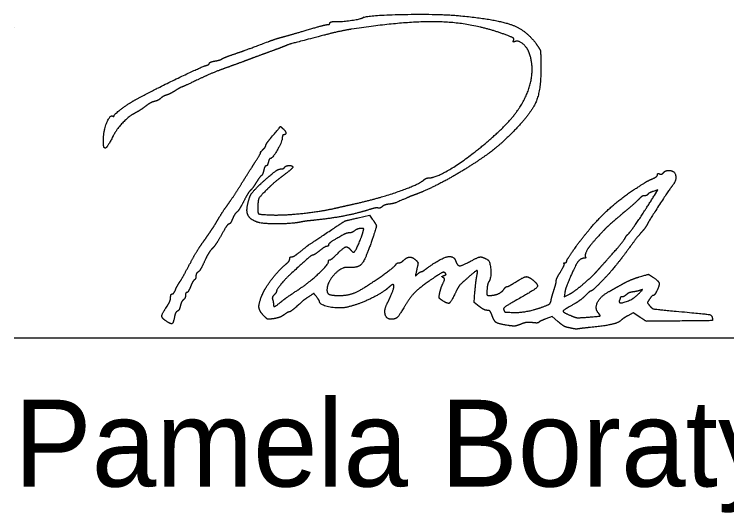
# Model space of a CAD drawing. Extents: x -8.3 to 34, y 0 to 22.
# Drawn here: x 24.426 to 25.575, y 2.669 to 3.473 of the extents above; entities that cross this region are included whole.
import ezdxf

# ---------------------------------------------------------------- set-up
doc = ezdxf.new("R2010")
doc.units = 0
doc.layers.add('SH_Data', color=7, linetype='Continuous')
doc.layers.add('SH_Text', color=7, linetype='Continuous')

msp = doc.modelspace()

# ---------------------------------------------------------------- linework, layer by layer
at = {"layer": 'SH_Data'}
for p, q in [((24.4262, 3.4514), (24.4262, 3.4514)), ((24.4262, 2.9514), (27.9262, 2.9514))]:
    msp.add_line(p, q, dxfattribs=at)
at = {"layer": 'SH_Text'}
for points in [[(25.458, 3.1809), (25.4634, 3.1898), (25.4561, 3.1872)], [(24.9807, 3.1447), (24.9987, 3.1488), (25.0034, 3.1426)], [(25.1757, 3.0019), (25.1673, 3.0082), (25.1688, 3.0253)], [(25.3137, 3.0239), (25.3126, 3.0174), (25.3213, 3.0218)], [(25.4345, 2.9846), (25.4238, 2.9914), (25.4155, 2.9869)], [(25.3026, 2.9776), (25.2935, 2.9858), (25.2829, 2.9818)]]:
    msp.add_lwpolyline(points, dxfattribs=at)
for points in [[(24.9881, 3.4673), (24.9949, 3.4715), (25.1119, 3.4738), (25.1463, 3.4704)], [(25.1463, 3.4704), (25.2056, 3.4645), (25.2531, 3.4463), (25.2689, 3.4232)], [(24.9314, 3.4563), (24.9334, 3.4563), (24.9351, 3.4575), (24.9351, 3.4588)], [(24.9351, 3.4588), (24.9351, 3.4602), (24.9392, 3.4612), (24.9441, 3.4611)], [(24.9441, 3.4611), (24.9537, 3.4608), (24.9847, 3.4652), (24.9881, 3.4673)], [(25.2188, 3.4396), (25.1683, 3.4586), (25.0603, 3.4626), (24.9699, 3.4488)], [(24.8595, 3.4365), (24.8648, 3.4379), (24.8823, 3.4429), (24.8984, 3.4477)], [(24.8984, 3.4477), (24.9145, 3.4524), (24.9293, 3.4563), (24.9314, 3.4563)], [(24.9699, 3.4488), (24.9607, 3.4474), (24.9407, 3.4431), (24.9255, 3.4391)], [(24.8355, 3.4287), (24.8434, 3.4317), (24.8542, 3.4352), (24.8595, 3.4365)], [(24.9255, 3.4391), (24.8745, 3.4259), (24.8702, 3.4247), (24.8595, 3.4204)], [(25.2311, 3.431), (25.2321, 3.4335), (25.2287, 3.4359), (25.2188, 3.4396)], [(24.7791, 3.4081), (24.7938, 3.4132), (24.8003, 3.4156), (24.8355, 3.4287)], [(25.2335, 3.4289), (25.2309, 3.4279), (25.2302, 3.4286), (25.2311, 3.431)], [(25.2569, 3.409), (25.2537, 3.4188), (25.2392, 3.4311), (25.2335, 3.4289)], [(25.2689, 3.4232), (25.2739, 3.416), (25.2748, 3.4116), (25.2751, 3.3938)], [(24.8367, 3.4119), (24.8268, 3.4083), (24.8117, 3.4027), (24.8031, 3.3995)], [(24.8595, 3.4204), (24.8569, 3.4193), (24.8466, 3.4155), (24.8367, 3.4119)], [(24.7497, 3.3975), (24.7547, 3.3984), (24.7598, 3.4), (24.7611, 3.401)], [(24.7611, 3.401), (24.7624, 3.4019), (24.7705, 3.4052), (24.7791, 3.4081)], [(24.8031, 3.3995), (24.7945, 3.3962), (24.7783, 3.3903), (24.7671, 3.3863)], [(25.2114, 3.2878), (25.2424, 3.3172), (25.2662, 3.3808), (25.2569, 3.409)], [(24.6231, 3.3359), (24.6534, 3.3522), (24.727, 3.3878), (24.7353, 3.3903)], [(24.7353, 3.3903), (24.7383, 3.3912), (24.7407, 3.3928), (24.7407, 3.3938)], [(24.7407, 3.3938), (24.7407, 3.3949), (24.7448, 3.3966), (24.7497, 3.3975)], [(25.2751, 3.3938), (25.2759, 3.353), (25.2598, 3.3133), (25.2304, 3.2834)], [(24.7671, 3.3863), (24.7559, 3.3823), (24.7356, 3.3738), (24.7219, 3.3673)], [(24.7219, 3.3673), (24.7082, 3.3608), (24.6966, 3.3555), (24.6961, 3.3555)], [(24.6961, 3.3555), (24.6955, 3.3555), (24.691, 3.353), (24.6861, 3.3499)], [(24.6712, 3.3424), (24.668, 3.3414), (24.6639, 3.339), (24.6621, 3.3372)], [(24.6861, 3.3499), (24.6812, 3.3468), (24.6745, 3.3434), (24.6712, 3.3424)], [(24.5871, 3.3093), (24.5871, 3.3115), (24.6125, 3.3302), (24.6231, 3.3359)], [(24.6524, 3.3324), (24.6488, 3.3315), (24.6421, 3.3279), (24.6375, 3.3243)], [(24.6621, 3.3372), (24.6603, 3.3354), (24.6559, 3.3332), (24.6524, 3.3324)], [(24.6375, 3.3243), (24.6329, 3.3207), (24.6258, 3.3161), (24.6216, 3.314)], [(24.57, 3.2715), (24.5701, 3.2846), (24.5807, 3.3112), (24.5848, 3.3087)], [(24.5848, 3.3087), (24.5861, 3.3079), (24.5871, 3.3082), (24.5871, 3.3093)], [(24.6216, 3.314), (24.6112, 3.3086), (24.5913, 3.2878), (24.5851, 3.2757)], [(24.8373, 3.2704), (24.8559, 3.2925), (24.8552, 3.292), (24.8593, 3.2886)], [(24.8593, 3.2886), (24.8635, 3.285), (24.8645, 3.2787), (24.8607, 3.2787)], [(25.0947, 3.2091), (25.1088, 3.2091), (25.1769, 3.255), (25.2114, 3.2878)], [(24.5851, 3.2757), (24.5785, 3.2628), (24.5732, 3.2559), (24.5713, 3.2578)], [(24.8583, 3.2737), (24.8583, 3.2681), (24.8424, 3.2403), (24.8392, 3.2403)], [(24.8607, 3.2787), (24.8594, 3.2787), (24.8583, 3.2765), (24.8583, 3.2737)], [(25.2304, 3.2834), (25.2118, 3.2645), (25.1794, 3.2396), (25.1489, 3.2207)], [(24.5713, 3.2578), (24.5705, 3.2586), (24.5699, 3.2647), (24.57, 3.2715)], [(24.8271, 3.2547), (24.8298, 3.2574), (24.8319, 3.2605), (24.8319, 3.2617)], [(24.8319, 3.2617), (24.8319, 3.2629), (24.8344, 3.2668), (24.8373, 3.2704)], [(24.8234, 3.2499), (24.8228, 3.2499), (24.8245, 3.2521), (24.8271, 3.2547)], [(24.8144, 3.2343), (24.8199, 3.2429), (24.824, 3.2499), (24.8234, 3.2499)], [(24.8392, 3.2403), (24.8381, 3.2403), (24.8366, 3.2376), (24.8357, 3.2343)], [(24.7923, 3.1993), (24.7989, 3.2099), (24.8089, 3.2257), (24.8144, 3.2343)], [(24.8321, 3.2283), (24.8309, 3.2283), (24.8292, 3.2251), (24.8283, 3.2212)], [(24.8357, 3.2343), (24.8349, 3.231), (24.8333, 3.2283), (24.8321, 3.2283)], [(24.8619, 3.2259), (24.8637, 3.2289), (24.8751, 3.2292), (24.8751, 3.2263)], [(24.8235, 3.1994), (24.8392, 3.214), (24.852, 3.2235), (24.8559, 3.2235)], [(24.8283, 3.2212), (24.8275, 3.2172), (24.8257, 3.2134), (24.8244, 3.2126)], [(24.8559, 3.2235), (24.8584, 3.2235), (24.8611, 3.2246), (24.8619, 3.2259)], [(24.8751, 3.2263), (24.8751, 3.2252), (24.8684, 3.2193), (24.8601, 3.2132)], [(25.1489, 3.2207), (25.1297, 3.2089), (25.0884, 3.1879), (25.0743, 3.1828)], [(25.4631, 3.2141), (25.4631, 3.2156), (25.4647, 3.2163), (25.4666, 3.2155)], [(25.4666, 3.2155), (25.4684, 3.2148), (25.4713, 3.2158), (25.4728, 3.2177)], [(25.4728, 3.2177), (25.4744, 3.2196), (25.4781, 3.2211), (25.481, 3.2211)], [(25.481, 3.2211), (25.4905, 3.2211), (25.4942, 3.2051), (25.4868, 3.1961)], [(24.8244, 3.2126), (24.8232, 3.2118), (24.8194, 3.2066), (24.816, 3.2011)], [(24.8601, 3.2132), (24.8519, 3.2071), (24.8394, 3.1962), (24.8323, 3.1891)], [(24.9747, 3.1672), (25.0117, 3.1754), (25.0779, 3.1983), (25.0865, 3.2058)], [(25.0865, 3.2058), (25.0886, 3.2076), (25.0923, 3.2091), (25.0947, 3.2091)], [(25.4263, 3.1908), (25.4453, 3.203), (25.4471, 3.2041), (25.4553, 3.2078)], [(25.4553, 3.2078), (25.4596, 3.2097), (25.4631, 3.2126), (25.4631, 3.2141)], [(24.7706, 3.1663), (24.7759, 3.1738), (24.7857, 3.1886), (24.7923, 3.1993)], [(24.8022, 3.1647), (24.8049, 3.1778), (24.8111, 3.1878), (24.8235, 3.1994)], [(24.816, 3.2011), (24.8126, 3.1956), (24.8085, 3.1901), (24.8068, 3.1887)], [(25.4868, 3.1961), (25.4827, 3.1911), (25.4498, 3.1407), (25.4467, 3.1345)], [(24.8068, 3.1887), (24.8051, 3.1874), (24.8005, 3.1798), (24.7964, 3.1718)], [(24.8323, 3.1891), (24.8216, 3.1781), (24.8195, 3.1744), (24.8189, 3.1662)], [(25.0743, 3.1828), (25.0697, 3.1811), (25.0627, 3.1784), (25.0587, 3.1766)], [(25.3317, 3.0982), (25.354, 3.129), (25.399, 3.1731), (25.4263, 3.1908)], [(25.4474, 3.1825), (25.4466, 3.1813), (25.4443, 3.1803), (25.4421, 3.1803)], [(25.4561, 3.1872), (25.452, 3.1858), (25.4481, 3.1837), (25.4474, 3.1825)], [(24.7964, 3.1718), (24.7924, 3.1638), (24.7873, 3.1558), (24.7852, 3.154)], [(25.0587, 3.1766), (25.0416, 3.1692), (25.0367, 3.1675), (25.0301, 3.1667)], [(25.4332, 3.1749), (25.4305, 3.172), (25.4181, 3.1609), (25.4055, 3.1504)], [(25.4152, 3.1179), (25.4181, 3.1199), (25.4463, 3.1614), (25.458, 3.1809)], [(25.4421, 3.1803), (25.4399, 3.1803), (25.4359, 3.1779), (25.4332, 3.1749)], [(24.7539, 3.1407), (24.7577, 3.1473), (24.7652, 3.1589), (24.7706, 3.1663)], [(24.8175, 3.1379), (24.8071, 3.1418), (24.8, 3.1542), (24.8022, 3.1647)], [(24.8189, 3.1662), (24.8181, 3.1528), (24.8221, 3.1499), (24.8427, 3.1493)], [(24.8427, 3.1493), (24.862, 3.1488), (24.9198, 3.1549), (24.9411, 3.1597)], [(24.9411, 3.1597), (24.949, 3.1615), (24.9642, 3.1649), (24.9747, 3.1672)], [(25.0125, 3.1605), (25.0109, 3.1611), (25.0028, 3.1594), (24.9945, 3.1567)], [(25.0193, 3.1627), (25.0172, 3.1608), (25.0142, 3.1599), (25.0125, 3.1605)], [(25.0301, 3.1667), (25.0263, 3.1663), (25.0214, 3.1645), (25.0193, 3.1627)], [(24.7852, 3.154), (24.783, 3.1522), (24.7797, 3.1471), (24.7779, 3.1427)], [(24.9945, 3.1567), (24.9781, 3.1515), (24.933, 3.143), (24.9092, 3.1407)], [(25.4055, 3.1504), (25.3859, 3.1338), (25.3742, 3.1225), (25.3575, 3.1036)], [(24.7408, 3.1201), (24.7441, 3.1249), (24.75, 3.1341), (24.7539, 3.1407)], [(24.7779, 3.1427), (24.7761, 3.1383), (24.7735, 3.1347), (24.7722, 3.1347)], [(24.8888, 3.138), (24.875, 3.135), (24.8256, 3.1349), (24.8175, 3.1379)], [(24.9092, 3.1407), (24.9008, 3.1399), (24.8917, 3.1387), (24.8888, 3.138)], [(24.9267, 3.1183), (24.9584, 3.1393), (24.9598, 3.14), (24.9807, 3.1447)], [(25.0034, 3.1426), (25.01, 3.1338), (25.0098, 3.1289), (25.0021, 3.1064)], [(24.7722, 3.1347), (24.7709, 3.1347), (24.7655, 3.1268), (24.7602, 3.1172)], [(24.9749, 3.1239), (24.9723, 3.1219), (24.9684, 3.1203), (24.9661, 3.1203)], [(24.9848, 3.1275), (24.9819, 3.1274), (24.9774, 3.1258), (24.9749, 3.1239)], [(24.9881, 3.1209), (24.9898, 3.1267), (24.9893, 3.1275), (24.9848, 3.1275)], [(25.4467, 3.1345), (25.4449, 3.131), (25.441, 3.1256), (25.438, 3.1223)], [(24.7273, 3.1009), (24.7314, 3.1067), (24.7375, 3.1153), (24.7408, 3.1201)], [(24.7602, 3.1172), (24.7548, 3.1075), (24.7482, 3.0975), (24.7453, 3.095)], [(24.8875, 3.0904), (24.9012, 3.1014), (24.8993, 3.1), (24.9267, 3.1183)], [(24.9564, 3.1172), (24.942, 3.1093), (24.9327, 3.1029), (24.9327, 3.1009)], [(24.9661, 3.1203), (24.9639, 3.1203), (24.9595, 3.1189), (24.9564, 3.1172)], [(24.9734, 3.0891), (24.9752, 3.0891), (24.9849, 3.1103), (24.9881, 3.1209)], [(25.38, 3.075), (25.3954, 3.0921), (25.4089, 3.1085), (25.4113, 3.1128)], [(25.4113, 3.1128), (25.4125, 3.115), (25.4143, 3.1173), (25.4152, 3.1179)], [(25.438, 3.1223), (25.435, 3.1191), (25.4261, 3.1078), (25.4182, 3.0971)], [(24.7084, 3.0687), (24.7147, 3.0806), (24.7232, 3.0951), (24.7273, 3.1009)], [(24.9327, 3.1009), (24.9327, 3.0997), (24.9315, 3.0987), (24.9301, 3.0987)], [(25.0021, 3.1064), (24.9919, 3.0765), (24.9799, 3.0634), (24.9639, 3.0648)], [(25.3575, 3.1036), (25.3517, 3.097), (25.3454, 3.0841), (25.3469, 3.0817)], [(24.7453, 3.095), (24.7425, 3.0924), (24.7369, 3.0833), (24.733, 3.0747)], [(24.8737, 3.0819), (24.8756, 3.0819), (24.8818, 3.0857), (24.8875, 3.0904)], [(24.9183, 3.0915), (24.9133, 3.0876), (24.9083, 3.0843), (24.9072, 3.0843)], [(24.9301, 3.0987), (24.9286, 3.0987), (24.9233, 3.0955), (24.9183, 3.0915)], [(24.9471, 3.0867), (24.9573, 3.0969), (24.9638, 3.0987), (24.9687, 3.0927)], [(24.9687, 3.0927), (24.9704, 3.0908), (24.9725, 3.0891), (24.9734, 3.0891)], [(25.3167, 3.0749), (25.3167, 3.0763), (25.3235, 3.0868), (25.3317, 3.0982)], [(25.4182, 3.0971), (25.4104, 3.0865), (25.4027, 3.0763), (25.4012, 3.0745)], [(24.8649, 3.0707), (24.8679, 3.0731), (24.8703, 3.0766), (24.8703, 3.0785)], [(24.8703, 3.0785), (24.8703, 3.0804), (24.8718, 3.0819), (24.8737, 3.0819)], [(24.9072, 3.0843), (24.9053, 3.0843), (24.8968, 3.0771), (24.8715, 3.0538)], [(24.9351, 3.0771), (24.9364, 3.0771), (24.9418, 3.0815), (24.9471, 3.0867)], [(25.0539, 3.0762), (25.0589, 3.0812), (25.0688, 3.0813), (25.0738, 3.0763)], [(25.0919, 3.0637), (25.1121, 3.0788), (25.1348, 3.0844), (25.1378, 3.075)], [(25.1616, 3.0746), (25.1736, 3.0813), (25.1808, 3.082), (25.189, 3.0774)], [(25.3446, 3.0795), (25.3383, 3.0795), (25.3287, 3.0644), (25.3167, 3.0351)], [(25.3469, 3.0817), (25.3476, 3.0805), (25.3466, 3.0795), (25.3446, 3.0795)], [(24.6929, 3.0411), (24.6951, 3.0444), (24.7021, 3.0569), (24.7084, 3.0687)], [(24.733, 3.0747), (24.7291, 3.0662), (24.7244, 3.0583), (24.7225, 3.0572)], [(24.8268, 3.0225), (24.8313, 3.0329), (24.8546, 3.0624), (24.8649, 3.0707)], [(24.8867, 3.0306), (24.9022, 3.041), (24.9327, 3.0697), (24.9327, 3.074)], [(24.9327, 3.074), (24.9327, 3.0757), (24.9338, 3.0771), (24.9351, 3.0771)], [(24.9987, 3.0375), (25.0173, 3.0498), (25.0397, 3.0665), (25.0414, 3.0693)], [(25.0414, 3.0693), (25.0425, 3.071), (25.0449, 3.0723), (25.0467, 3.0723)], [(25.0467, 3.0723), (25.0485, 3.0723), (25.0517, 3.0741), (25.0539, 3.0762)], [(25.0738, 3.0763), (25.0769, 3.0732), (25.0772, 3.0707), (25.0751, 3.0615)], [(25.1378, 3.075), (25.1403, 3.0674), (25.1483, 3.0673), (25.1616, 3.0746)], [(25.189, 3.0774), (25.1934, 3.0749), (25.1951, 3.0469), (25.1912, 3.0417)], [(25.307, 3.058), (25.3108, 3.0643), (25.3134, 3.0701), (25.3126, 3.0709)], [(25.3126, 3.0709), (25.3118, 3.0717), (25.3124, 3.0723), (25.3139, 3.0723)], [(25.3139, 3.0723), (25.3155, 3.0723), (25.3167, 3.0735), (25.3167, 3.0749)], [(25.3644, 3.0575), (25.3676, 3.0611), (25.3746, 3.0689), (25.38, 3.075)], [(25.4012, 3.0745), (25.3879, 3.058), (25.3834, 3.0529), (25.3715, 3.0407)], [(24.7225, 3.0572), (24.7206, 3.0562), (24.7191, 3.0533), (24.7191, 3.0508)], [(24.9639, 3.0648), (24.9535, 3.0657), (24.9303, 3.0403), (24.9303, 3.028)], [(25.0751, 3.0615), (25.0727, 3.0513), (25.0728, 3.0508), (25.0766, 3.0543)], [(25.0766, 3.0543), (25.0789, 3.0563), (25.0815, 3.0579), (25.0825, 3.0579)], [(25.0825, 3.0579), (25.0835, 3.0579), (25.0877, 3.0605), (25.0919, 3.0637)], [(25.1206, 3.0559), (25.1188, 3.0577), (25.1129, 3.0549), (25.1004, 3.0464)], [(25.1189, 3.0517), (25.1219, 3.0528), (25.1224, 3.054), (25.1206, 3.0559)], [(25.1718, 3.0501), (25.1736, 3.0596), (25.171, 3.06), (25.1617, 3.0518)], [(25.2999, 3.0433), (25.2999, 3.0451), (25.3031, 3.0518), (25.307, 3.058)], [(25.3443, 3.0387), (25.3522, 3.0455), (25.3613, 3.054), (25.3644, 3.0575)], [(24.7166, 3.0447), (24.7153, 3.0438), (24.7124, 3.0389), (24.7104, 3.0337)], [(24.7191, 3.0508), (24.7191, 3.0483), (24.718, 3.0455), (24.7166, 3.0447)], [(24.8715, 3.0538), (24.8624, 3.0454), (24.8487, 3.0284), (24.8487, 3.0254)], [(25.1004, 3.0464), (25.0806, 3.033), (25.0634, 3.0159), (25.0551, 3.0015)], [(25.1177, 3.0482), (25.1155, 3.0496), (25.1158, 3.0505), (25.1189, 3.0517)], [(25.117, 3.0384), (25.1199, 3.0446), (25.12, 3.0468), (25.1177, 3.0482)], [(25.1617, 3.0518), (25.1458, 3.0378), (25.142, 3.0334), (25.1365, 3.022)], [(25.1688, 3.0253), (25.1696, 3.0347), (25.1709, 3.0459), (25.1718, 3.0501)], [(25.2625, 3.0441), (25.2722, 3.0365), (25.2654, 3.0286), (25.2338, 3.0109)], [(25.2343, 3.0411), (25.2473, 3.0494), (25.2549, 3.0502), (25.2625, 3.0441)], [(25.4043, 3.0367), (25.4122, 3.0412), (25.4254, 3.0469), (25.4336, 3.0494)], [(25.4336, 3.0494), (25.4477, 3.0536), (25.4489, 3.0536), (25.4547, 3.0498)], [(25.4547, 3.0498), (25.4643, 3.0435), (25.4667, 3.0361), (25.4621, 3.0271)], [(24.6861, 3.0285), (24.6876, 3.0322), (24.6907, 3.0378), (24.6929, 3.0411)], [(24.7104, 3.0337), (24.7083, 3.0286), (24.7056, 3.0243), (24.7045, 3.0243)], [(24.9503, 3.0195), (24.9633, 3.0195), (24.9824, 3.0266), (24.9987, 3.0375)], [(25.0307, 3.0333), (25.0211, 3.0242), (24.9824, 3.0054), (24.9639, 3.0009)], [(25.0278, 3.0075), (25.0319, 3.0152), (25.0383, 3.0315), (25.0383, 3.0342)], [(25.0383, 3.0342), (25.0383, 3.0373), (25.0344, 3.0368), (25.0307, 3.0333)], [(25.1119, 3.0228), (25.1127, 3.0269), (25.115, 3.034), (25.117, 3.0384)], [(25.1912, 3.0417), (25.19, 3.0401), (25.1886, 3.0344), (25.1883, 3.0291)], [(25.2152, 3.0291), (25.2171, 3.0318), (25.2196, 3.0339), (25.2208, 3.0339)], [(25.2208, 3.0339), (25.222, 3.0339), (25.2281, 3.0372), (25.2343, 3.0411)], [(25.2964, 3.0291), (25.2984, 3.0351), (25.2999, 3.0414), (25.2999, 3.0433)], [(25.3167, 3.0351), (25.3156, 3.0325), (25.3142, 3.0274), (25.3137, 3.0239)], [(25.3213, 3.0218), (25.326, 3.0243), (25.3364, 3.0319), (25.3443, 3.0387)], [(25.3715, 3.0407), (25.364, 3.033), (25.357, 3.0267), (25.3559, 3.0267)], [(25.3848, 3.0257), (25.3876, 3.0272), (25.3964, 3.0322), (25.4043, 3.0367)], [(24.6783, 3.0163), (24.6783, 3.0194), (24.6794, 3.0219), (24.6808, 3.0219)], [(24.6808, 3.0219), (24.6821, 3.0219), (24.6845, 3.0249), (24.6861, 3.0285)], [(24.7045, 3.0243), (24.7033, 3.0243), (24.7023, 3.0223), (24.7023, 3.0198)], [(24.8285, 2.9868), (24.8209, 2.9944), (24.8203, 3.0072), (24.8268, 3.0225)], [(24.8487, 3.0254), (24.8487, 3.0246), (24.847, 3.0223), (24.845, 3.0203)], [(24.8551, 3.0082), (24.8627, 3.0143), (24.8679, 3.0181), (24.8867, 3.0306)], [(24.9137, 3.017), (24.9093, 3.0228), (24.9092, 3.0228), (24.9024, 3.0184)], [(24.9303, 3.028), (24.9303, 3.0229), (24.9381, 3.0195), (24.9503, 3.0195)], [(25.1165, 3.0112), (25.1116, 3.0145), (25.1108, 3.0165), (25.1119, 3.0228)], [(25.1365, 3.022), (25.1299, 3.0083), (25.125, 3.0057), (25.1165, 3.0112)], [(25.1883, 3.0291), (25.1878, 3.0216), (25.1885, 3.0195), (25.1916, 3.0195)], [(25.1916, 3.0195), (25.1999, 3.0195), (25.2119, 3.0244), (25.2152, 3.0291)], [(25.2917, 3.0121), (25.2923, 3.0155), (25.2945, 3.0232), (25.2964, 3.0291)], [(25.3559, 3.0267), (25.3548, 3.0267), (25.351, 3.0236), (25.3473, 3.0198)], [(25.3677, 2.9913), (25.3616, 2.9987), (25.3714, 3.0185), (25.3848, 3.0257)], [(25.4017, 3.0114), (25.3992, 3.0049), (25.4247, 3.0138), (25.4331, 3.0225)], [(25.4127, 3.0207), (25.4105, 3.0188), (25.4075, 3.0171), (25.4059, 3.0171)], [(25.4237, 3.0253), (25.4199, 3.0248), (25.4149, 3.0227), (25.4127, 3.0207)], [(25.4355, 3.028), (25.4329, 3.027), (25.4276, 3.0258), (25.4237, 3.0253)], [(25.4331, 3.0225), (25.4386, 3.0281), (25.4392, 3.0294), (25.4355, 3.028)], [(25.4621, 3.0271), (25.46, 3.0229), (25.4573, 3.0195), (25.4561, 3.0195)], [(24.6725, 3.0021), (24.6757, 3.0068), (24.6783, 3.0132), (24.6783, 3.0163)], [(24.6989, 3.0125), (24.697, 3.0109), (24.6947, 3.0064), (24.6939, 3.0024)], [(24.7023, 3.0198), (24.7023, 3.0174), (24.7008, 3.014), (24.6989, 3.0125)], [(24.845, 3.0203), (24.8429, 3.0182), (24.8419, 3.015), (24.8426, 3.013)], [(24.8426, 3.013), (24.8433, 3.0111), (24.8439, 3.008), (24.8439, 3.0061)], [(24.9024, 3.0184), (24.8942, 3.013), (24.8917, 3.011), (24.8805, 3.0009)], [(24.9183, 3.0096), (24.9182, 3.0105), (24.9162, 3.0138), (24.9137, 3.017)], [(24.9639, 3.0009), (24.9511, 2.9978), (24.9185, 3.004), (24.9183, 3.0096)], [(25.2338, 3.0109), (25.2206, 3.0034), (25.2143, 2.9986), (25.2152, 2.9964)], [(25.279, 3.0014), (25.2878, 3.0048), (25.2907, 3.0073), (25.2917, 3.0121)], [(25.3473, 3.0198), (25.3437, 3.016), (25.3356, 3.0098), (25.3294, 3.0062)], [(25.4031, 3.0161), (25.4031, 3.0156), (25.4025, 3.0135), (25.4017, 3.0114)], [(25.4059, 3.0171), (25.4044, 3.0171), (25.4031, 3.0167), (25.4031, 3.0161)], [(25.4503, 3.0137), (25.4468, 3.0084), (25.4468, 3.0075), (25.4506, 3.0028)], [(25.4561, 3.0195), (25.455, 3.0195), (25.4524, 3.0169), (25.4503, 3.0137)], [(24.6708, 2.9784), (24.6638, 2.9832), (24.6643, 2.9899), (24.6725, 3.0021)], [(24.6939, 3.0024), (24.693, 2.9985), (24.6909, 2.9947), (24.6891, 2.994)], [(24.8439, 3.0061), (24.8439, 3.0013), (24.8474, 3.0019), (24.8551, 3.0082)], [(24.8805, 3.0009), (24.8757, 2.9967), (24.8708, 2.9931), (24.8697, 2.9931)], [(25.0345, 2.9811), (25.0261, 2.9811), (25.0221, 2.997), (25.0278, 3.0075)], [(25.0551, 3.0015), (25.0469, 2.9874), (25.0406, 2.9811), (25.0345, 2.9811)], [(25.1887, 2.9955), (25.1861, 2.9955), (25.1802, 2.9984), (25.1757, 3.0019)], [(25.2291, 2.9921), (25.2397, 2.9915), (25.2658, 2.9964), (25.279, 3.0014)], [(25.3294, 3.0062), (25.3114, 2.9958), (25.3104, 2.9925), (25.3233, 2.987)], [(25.4506, 3.0028), (25.4543, 2.9983), (25.4592, 2.9973), (25.4931, 2.9941)], [(24.6891, 2.994), (24.6874, 2.9934), (24.6853, 2.9892), (24.6845, 2.9848)], [(24.8447, 2.9821), (24.836, 2.9808), (24.8338, 2.9814), (24.8285, 2.9868)], [(24.8612, 2.9884), (24.8577, 2.9858), (24.8502, 2.983), (24.8447, 2.9821)], [(24.8697, 2.9931), (24.8686, 2.9931), (24.8648, 2.991), (24.8612, 2.9884)], [(25.1962, 2.9877), (25.1943, 2.9929), (25.1918, 2.9955), (25.1887, 2.9955)], [(25.2216, 2.9712), (25.2065, 2.9736), (25.1997, 2.9781), (25.1962, 2.9877)], [(25.2152, 2.9964), (25.2165, 2.993), (25.2172, 2.9928), (25.2291, 2.9921)], [(25.3233, 2.987), (25.3302, 2.984), (25.3366, 2.9834), (25.3501, 2.9845)], [(25.3501, 2.9845), (25.3697, 2.9861), (25.3714, 2.9868), (25.3677, 2.9913)], [(25.4155, 2.9869), (25.4109, 2.9844), (25.4056, 2.9808), (25.4038, 2.979)], [(25.4931, 2.9941), (25.5422, 2.9896), (25.5505, 2.988), (25.5514, 2.9832)], [(24.6845, 2.9848), (24.6827, 2.9751), (24.6785, 2.9731), (24.6708, 2.9784)], [(25.2615, 2.9757), (25.2558, 2.9765), (25.2485, 2.9755), (25.2427, 2.9732)], [(25.2716, 2.9761), (25.2712, 2.9752), (25.2667, 2.975), (25.2615, 2.9757)], [(25.2829, 2.9818), (25.2771, 2.9795), (25.272, 2.9769), (25.2716, 2.9761)], [(25.3173, 2.9681), (25.3143, 2.9687), (25.3077, 2.973), (25.3026, 2.9776)], [(25.4038, 2.979), (25.4, 2.9753), (25.3785, 2.9704), (25.3551, 2.968)], [(25.4811, 2.9781), (25.4454, 2.9778), (25.445, 2.9778), (25.4345, 2.9846)], [(25.5514, 2.9832), (25.5522, 2.979), (25.5503, 2.9789), (25.4811, 2.9781)], [(25.2427, 2.9732), (25.2357, 2.9704), (25.2301, 2.9699), (25.2216, 2.9712)], [(25.3275, 2.9659), (25.3249, 2.9665), (25.3203, 2.9675), (25.3173, 2.9681)], [(25.3359, 2.9657), (25.3339, 2.9653), (25.3302, 2.9654), (25.3275, 2.9659)], [(25.3551, 2.968), (25.3465, 2.9671), (25.3379, 2.9661), (25.3359, 2.9657)]]:
    msp.add_open_spline(points, degree=2, dxfattribs=at)

# ---------------------------------------------------------------- texts
msp.add_text('Pamela Boratyn', height=0.14, dxfattribs=at).set_placement((24.4262, 2.7114))

doc.saveas('drawing.dxf')
